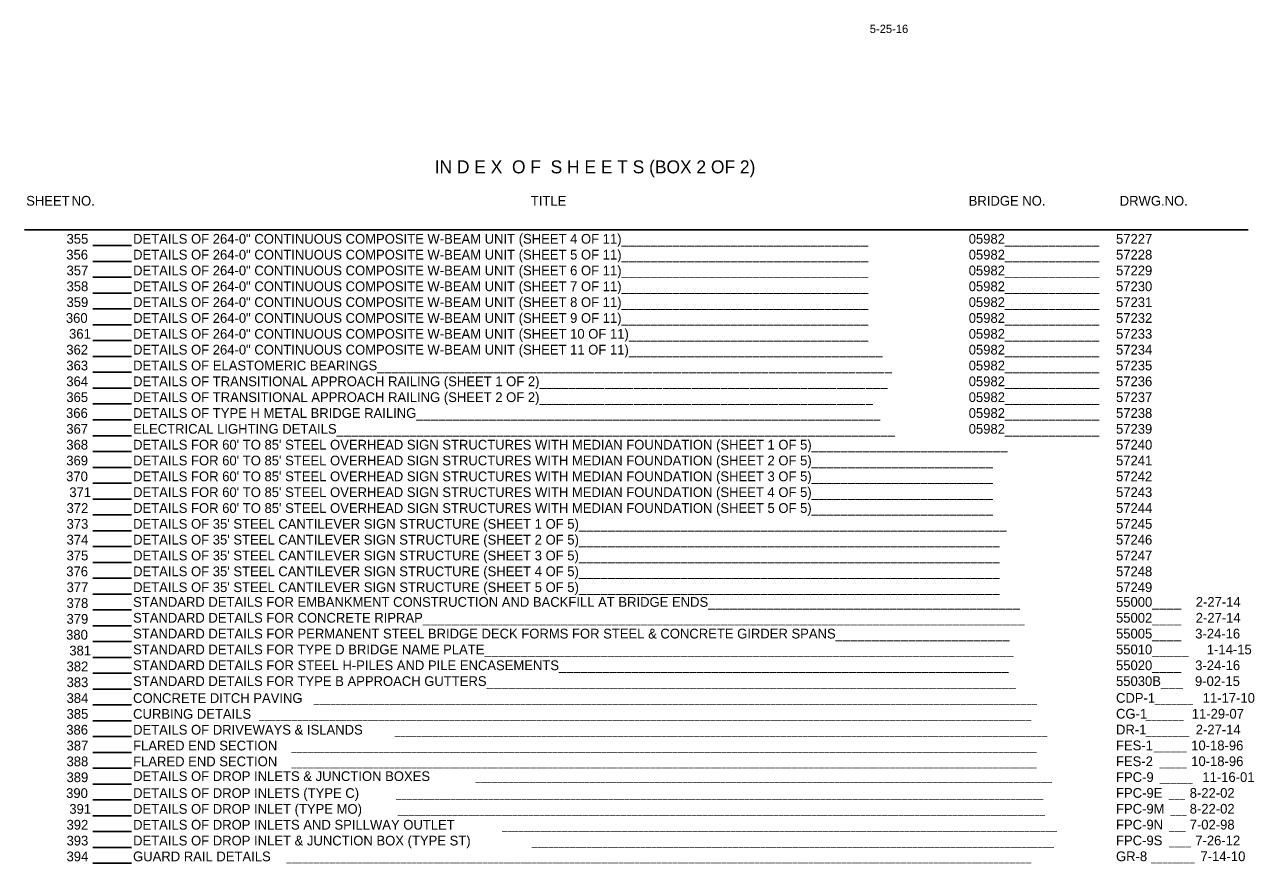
# Model space of a CAD drawing. Extents: x 1224738 to 1230974, y 151304 to 152345.
# Drawn here: x 1227314 to 1227963, y 151881 to 152323 of the extents above; entities that cross this region are included whole.
import ezdxf

# ---------------------------------------------------------------- set-up
doc = ezdxf.new("R2010")
doc.units = 0
for name, color, linetype in [('R_Border', 7, 'Continuous'), ('R_Border Notes', 7, 'Continuous'), ('R_Dimension', 7, 'Continuous')]:
    doc.layers.add(name, color=color, linetype=linetype)

msp = doc.modelspace()

# ---------------------------------------------------------------- linework, layer by layer
at = {"layer": 'R_Border Notes'}
msp.add_line((1227314.16, 152214.98), (1227314.16, 152214.98), dxfattribs=at)
at = {"layer": 'R_Dimension'}
for p, q in [((1227314.16, 152214.98), (1227959.93, 152214.98)), ((1227350.11, 152206.63), (1227370.59, 152206.63)), ((1227350.11, 152198.27), (1227370.59, 152198.27)), ((1227350.11, 152189.91), (1227370.59, 152189.91)), ((1227350.11, 152181.55), (1227370.59, 152181.55)), ((1227350.11, 152173.19), (1227370.59, 152173.19)), ((1227350.11, 152164.83), (1227370.59, 152164.83)), ((1227350.11, 152156.47), (1227370.59, 152156.47)), ((1227350.11, 152148.11), (1227370.59, 152148.11)), ((1227350.11, 152139.75), (1227370.59, 152139.75)), ((1227350.11, 152131.39), (1227370.59, 152131.39)), ((1227350.11, 152123.03), (1227370.59, 152123.03)), ((1227350.11, 152114.67), (1227370.59, 152114.67)), ((1227350.11, 152106.31), (1227370.59, 152106.31)), ((1227350.11, 152097.95), (1227370.59, 152097.95)), ((1227350.11, 152089.59), (1227370.59, 152089.59)), ((1227350.11, 152081.23), (1227370.59, 152081.23)), ((1227350.11, 152072.87), (1227370.59, 152072.87)), ((1227350.11, 152064.52), (1227370.59, 152064.52)), ((1227350.11, 152056.16), (1227370.59, 152056.16)), ((1227350.11, 152047.8), (1227370.59, 152047.8)), ((1227350.11, 152039.44), (1227370.59, 152039.44)), ((1227350.11, 152031.08), (1227370.59, 152031.08)), ((1227350.11, 152022.72), (1227370.59, 152022.72)), ((1227350.11, 152014.36), (1227370.59, 152014.36)), ((1227350.11, 152006), (1227370.59, 152006)), ((1227350.11, 151997.64), (1227370.59, 151997.64)), ((1227350.11, 151989.28), (1227370.59, 151989.28)), ((1227350.11, 151980.92), (1227370.59, 151980.92)), ((1227350.11, 151972.56), (1227370.59, 151972.56)), ((1227350.11, 151964.2), (1227370.59, 151964.2)), ((1227350.11, 151955.84), (1227370.59, 151955.84)), ((1227350.11, 151947.48), (1227370.59, 151947.48)), ((1227350.11, 151939.12), (1227370.59, 151939.12)), ((1227350.11, 151930.76), (1227370.59, 151930.76)), ((1227350.11, 151922.41), (1227370.59, 151922.41)), ((1227350.11, 151914.05), (1227370.59, 151914.05)), ((1227350.11, 151905.69), (1227370.59, 151905.69)), ((1227350.11, 151897.33), (1227370.59, 151897.33)), ((1227350.11, 151888.97), (1227370.59, 151888.97)), ((1227350.11, 151880.61), (1227370.59, 151880.61))]:
    msp.add_line(p, q, dxfattribs=at)

# ---------------------------------------------------------------- texts
at = {"layer": 'R_Border'}
msp.add_text('5-25-16', height=4.396, dxfattribs=at).set_placement((1227760.18, 152318.84))
at = {"layer": 'R_Dimension'}
for s, height, p in [('I', 6.86, (1227530.59, 152244.78)), (' N D E X  O F  S H E E T S (BOX 2 OF 2)', 6.859, (1227530.59, 152244.78)), ('SHEET', 5.144, (1227315, 152227.72)), (' NO.', 5.144, (1227337.07, 152227.72)), ('TITLE', 5.144, (1227581.31, 152227.72)), ('BRIDGE NO.', 5.144, (1227812.38, 152227.72)), ('DRWG.NO.', 5.144, (1227892.08, 152227.72)), ('355', 5.144, (1227336.3, 152207.65)), ('DETAILS OF 264-0" CONTINUOUS COMPOSITE W-BEAM UNIT (SHEET 4 OF 11)__________________________________', 5.1443, (1227371.42, 152207.65)), ('05982_____________', 5.1443, (1227812.38, 152207.65)), ('57227', 5.144, (1227890.12, 152207.65)), ('356', 5.144, (1227336.16, 152199.29)), ('DETAILS OF 264-0" CONTINUOUS COMPOSITE W-BEAM UNIT (SHEET 5 OF 11)__________________________________', 5.1443, (1227371.42, 152199.29)), ('05982_____________', 5.1443, (1227812.38, 152199.29)), ('57228', 5.144, (1227890.12, 152199.29)), ('357', 5.144, (1227336.3, 152190.94)), ('DETAILS OF 264-0" CONTINUOUS COMPOSITE W-BEAM UNIT (SHEET 6 OF 11)__________________________________', 5.1443, (1227371.42, 152190.94)), ('05982_____________', 5.1443, (1227812.38, 152190.94)), ('57229', 5.144, (1227890.12, 152190.94)), ('358', 5.144, (1227336.3, 152182.58)), ('DETAILS OF 264-0" CONTINUOUS COMPOSITE W-BEAM UNIT (SHEET 7 OF 11)__________________________________', 5.1443, (1227371.42, 152182.58)), ('05982_____________', 5.1443, (1227812.38, 152182.58)), ('57230', 5.144, (1227890.12, 152182.58)), ('359', 5.144, (1227336.28, 152174.22)), ('DETAILS OF 264-0" CONTINUOUS COMPOSITE W-BEAM UNIT (SHEET 8 OF 11)__________________________________', 5.1443, (1227371.42, 152174.22)), ('05982_____________', 5.1443, (1227812.38, 152174.22)), ('57231', 5.144, (1227890.12, 152174.22)), ('360', 5.144, (1227335.95, 152165.86)), ('DETAILS OF 264-0" CONTINUOUS COMPOSITE W-BEAM UNIT (SHEET 9 OF 11)__________________________________', 5.1443, (1227371.42, 152165.86)), ('05982_____________', 5.1443, (1227812.38, 152165.86)), ('57232', 5.144, (1227890.12, 152165.86)), ('361', 5.144, (1227337.64, 152157.5)), ('DETAILS OF 264-0" CONTINUOUS COMPOSITE W-BEAM UNIT (SHEET 10 OF 11)_________________________________', 5.1443, (1227371.42, 152157.5)), ('05982_____________', 5.1443, (1227812.38, 152157.5)), ('57233', 5.144, (1227890.12, 152157.5)), ('362', 5.144, (1227336.18, 152149.14)), ('DETAILS OF 264-0" CONTINUOUS COMPOSITE W-BEAM UNIT (SHEET 11 OF 11)___________________________________', 5.14425, (1227371.42, 152149.14)), ('05982_____________', 5.1443, (1227812.38, 152149.14)), ('57234', 5.144, (1227890.12, 152149.14)), ('363', 5.144, (1227336.18, 152140.78)), ('DETAILS OF ELASTOMERIC BEARINGS_______________________________________________________________________', 5.14425, (1227371.42, 152140.78)), ('05982_____________', 5.1443, (1227812.38, 152140.78)), ('57235', 5.144, (1227890.12, 152140.78)), ('364', 5.144, (1227336.18, 152132.42)), ('DETAILS OF TRANSITIONAL APPROACH RAILING (SHEET 1 OF 2)________________________________________________', 5.14425, (1227371.42, 152132.42)), ('05982_____________', 5.1443, (1227812.38, 152132.42)), ('57236', 5.144, (1227890.12, 152132.42)), ('365', 5.144, (1227336.18, 152124.06)), ('DETAILS OF TRANSITIONAL APPROACH RAILING (SHEET 2 OF 2)______________________________________________', 5.14425, (1227371.42, 152124.06)), ('05982_____________', 5.1443, (1227812.38, 152124.06)), ('57237', 5.144, (1227890.12, 152124.06)), ('366', 5.144, (1227336.04, 152115.7)), ('DETAILS OF TYPE H METAL BRIDGE RAILING________________________________________________________________', 5.14425, (1227371.42, 152115.7)), ('05982_____________', 5.1443, (1227812.38, 152115.7)), ('57238', 5.144, (1227890.12, 152115.7)), ('367', 5.144, (1227336.18, 152107.34)), ('ELECTRICAL LIGHTING DETAILS_____________________________________________________________________________', 5.14425, (1227371.42, 152107.34)), ('05982_____________', 5.1443, (1227812.38, 152107.34)), ('57239', 5.144, (1227890.12, 152107.34)), ('368', 5.144, (1227336.18, 152098.98)), ("DETAILS FOR 60' TO 85' STEEL OVERHEAD SIGN STRUCTURES WITH MEDIAN FOUNDATION (SHEET 1 OF 5)___________________________", 5.14425, (1227371.42, 152098.98)), ('57240', 5.144, (1227890.12, 152098.98)), ('369', 5.144, (1227336.16, 152090.62)), ("DETAILS FOR 60' TO 85' STEEL OVERHEAD SIGN STRUCTURES WITH MEDIAN FOUNDATION (SHEET 2 OF 5)_________________________", 5.14425, (1227371.42, 152090.62)), ('57241', 5.144, (1227890.12, 152090.62)), ('370', 5.144, (1227336.08, 152082.26)), ("DETAILS FOR 60' TO 85' STEEL OVERHEAD SIGN STRUCTURES WITH MEDIAN FOUNDATION (SHEET 3 OF 5)_________________________", 5.14425, (1227371.42, 152082.26)), ('57242', 5.144, (1227890.12, 152082.26)), ('371', 5.144, (1227337.76, 152073.9)), ("DETAILS FOR 60' TO 85' STEEL OVERHEAD SIGN STRUCTURES WITH MEDIAN FOUNDATION (SHEET 4 OF 5)_________________________", 5.14425, (1227371.42, 152073.9)), ('57243', 5.144, (1227890.12, 152073.9)), ('372', 5.144, (1227336.3, 152065.54)), ("DETAILS FOR 60' TO 85' STEEL OVERHEAD SIGN STRUCTURES WITH MEDIAN FOUNDATION (SHEET 5 OF 5)_________________________", 5.14425, (1227371.42, 152065.54)), ('57244', 5.144, (1227890.12, 152065.54)), ('373', 5.144, (1227336.3, 152057.18)), ("DETAILS OF 35' STEEL CANTILEVER SIGN STRUCTURE (SHEET 1 OF 5)___________________________________________________________", 5.14425, (1227371.42, 152057.19)), ('57245', 5.144, (1227890.12, 152057.18)), ('374', 5.144, (1227336.3, 152048.83)), ("DETAILS OF 35' STEEL CANTILEVER SIGN STRUCTURE (SHEET 2 OF 5)__________________________________________________________", 5.14425, (1227371.42, 152048.83)), ('57246', 5.144, (1227890.12, 152048.83)), ('375', 5.144, (1227336.3, 152040.47)), ("DETAILS OF 35' STEEL CANTILEVER SIGN STRUCTURE (SHEET 3 OF 5)__________________________________________________________", 5.14425, (1227371.42, 152040.47)), ('57247', 5.144, (1227890.12, 152040.47)), ('376', 5.144, (1227336.16, 152032.11)), ("DETAILS OF 35' STEEL CANTILEVER SIGN STRUCTURE (SHEET 4 OF 5)__________________________________________________________", 5.14425, (1227371.42, 152032.11)), ('57248', 5.144, (1227890.12, 152032.11)), ('377', 5.144, (1227336.3, 152023.75)), ("DETAILS OF 35' STEEL CANTILEVER SIGN STRUCTURE (SHEET 5 OF 5)__________________________________________________________", 5.14425, (1227371.42, 152023.75)), ('57249', 5.144, (1227890.12, 152023.75)), ('378', 5.144, (1227336.3, 152015.39)), ('STANDARD DETAILS FOR EMBANKMENT CONSTRUCTION AND BACKFILL AT BRIDGE ENDS___________________________________________', 5.14425, (1227371.42, 152015.97)), ('55000____', 5.144, (1227890.12, 152015.97)), ('2-27-14', 5.144, (1227932.19, 152015.97)), ('379', 5.144, (1227336.28, 152007.03)), ('STANDARD DETAILS FOR CONCRETE RIPRAP___________________________________________________________________________________', 5.14425, (1227371.42, 152007.61)), ('55002____', 5.144, (1227890.12, 152007.61)), ('2-27-14', 5.144, (1227932.19, 152007.61)), ('380', 5.144, (1227336.08, 151998.67)), ('STANDARD DETAILS FOR PERMANENT STEEL BRIDGE DECK FORMS FOR STEEL & CONCRETE GIRDER SPANS________________________', 5.14425, (1227371.42, 151999.25)), ('55005____', 5.144, (1227890.12, 151999.25)), ('3-24-16', 5.144, (1227931.91, 151999.25)), ('381', 5.144, (1227337.76, 151990.31)), ('STANDARD DETAILS FOR TYPE D BRIDGE NAME PLATE_________________________________________________________________________', 5.14425, (1227371.42, 151990.89)), ('55010_____', 5.144, (1227890.12, 151990.89)), ('1-14-15', 5.144, (1227938.03, 151990.89)), ('382', 5.144, (1227336.3, 151981.95)), ('STANDARD DETAILS FOR STEEL H-PILES AND PILE ENCASEMENTS______________________________________________________________', 5.14425, (1227371.42, 151982.53)), ('55020____', 5.144, (1227890.12, 151982.53)), ('3-24-16', 5.144, (1227931.91, 151982.53)), ('383', 5.144, (1227336.3, 151973.59)), ('STANDARD DETAILS FOR TYPE B APPROACH GUTTERS_________________________________________________________________________ ', 5.14425, (1227371.42, 151974.17)), ('55030B___', 5.144, (1227890.12, 151974.17)), ('9-02-15', 5.144, (1227931.79, 151974.17)), ('384', 5.144, (1227336.3, 151965.23)), ('CONCRETE DITCH PAVING', 5.1443, (1227371.42, 151965.23)), ('CDP-1', 5.144, (1227890.12, 151965.31)), ('11-17-10', 5.144, (1227935.88, 151965.31)), ('385', 5.144, (1227336.3, 151956.87)), ('CURBING DETAILS', 5.1443, (1227371.42, 151956.87)), ('_____________________________________________________________________________________________________________________________________', 3.85819, (1227466.77, 151965.23)), ('CG-1', 5.144, (1227890.12, 151956.95)), ('_______', 3.858, (1227910.62, 151965.31)), ('11-29-07', 5.144, (1227930.09, 151956.95)), ('386', 5.144, (1227336.16, 151948.51)), ('DETAILS OF DRIVEWAYS & ISLANDS', 5.1443, (1227371.42, 151948.51)), ('______________________________________________________________________________________________________________________________________________', 3.85819, (1227437.93, 151956.87)), ('DR-1', 5.144, (1227890.12, 151948.59)), ('_______', 3.858, (1227905.76, 151956.95)), ('2-27-14', 5.144, (1227932.19, 151948.59)), ('________________________________________________________________________________________________________________________', 3.85819, (1227509.47, 151948.51)), ('________', 3.858, (1227905.76, 151948.59)), ('387', 5.144, (1227336.3, 151940.15)), ('FLARED END SECTION', 5.1443, (1227371.42, 151940.15)), ('FES-1', 5.144, (1227890.12, 151940.23)), ('10-18-96', 5.144, (1227929.8, 151940.23)), ('388', 5.144, (1227336.3, 151931.79)), ('FLARED END SECTION', 5.1443, (1227371.42, 151931.79)), ('_________________________________________________________________________________________________________________________________________', 3.85819, (1227455.03, 151940.15)), ('FES-2', 5.144, (1227890.12, 151931.87)), ('______', 3.858, (1227910.13, 151940.23)), ('10-18-96', 5.144, (1227929.8, 151931.87)), ('389', 5.144, (1227336.28, 151923.43)), ('DETAILS OF DROP INLETS & JUNCTION BOXES', 5.1443, (1227371.42, 151924.01)), ('_________________________________________________________________________________________________________________________________________', 3.85819, (1227455.03, 151931.79)), ('FPC-9', 5.144, (1227890.12, 151923.51)), ('_____', 3.858, (1227913.05, 151931.87)), ('11-16-01', 5.144, (1227935.68, 151923.51)), ('__________________________________________________________________________________________________________', 3.85819, (1227552.08, 151924.01)), ('______', 3.858, (1227913.29, 151923.51)), ('390', 5.144, (1227336.08, 151915.07)), ('DETAILS OF DROP INLETS (TYPE C)', 5.1443, (1227371.42, 151915.08)), ('FPC-9E', 5.144, (1227890.12, 151915.15)), ('8-22-02', 5.144, (1227929, 151915.15)), ('391', 5.144, (1227337.76, 151906.72)), ('DETAILS OF DROP INLET (TYPE MO)', 5.1443, (1227371.42, 151906.72)), ('_______________________________________________________________________________________________________________________', 3.85819, (1227510.2, 151915.08)), ('FPC-9M', 5.144, (1227890.12, 151906.79)), ('___', 3.858, (1227917.91, 151915.15)), ('8-22-02', 5.144, (1227929, 151906.79)), ('392', 5.144, (1227336.3, 151898.36)), ('DETAILS OF DROP INLETS AND SPILLWAY OUTLET', 5.1443, (1227371.42, 151898.36)), ('_______________________________________________________________________________________________________________________', 3.85819, (1227511.17, 151906.72)), ('FPC-9N', 5.144, (1227890.12, 151898.43)), ('___', 3.858, (1227918.8, 151906.79)), ('7-02-98', 5.144, (1227929, 151898.43)), ('393', 5.144, (1227336.3, 151890)), ('DETAILS OF DROP INLET & JUNCTION BOX (TYPE ST)', 5.1443, (1227371.42, 151890)), ('______________________________________________________________________________________________________', 3.85819, (1227566.18, 151898.36)), ('FPC-9S', 5.144, (1227890.12, 151890.07)), ('___', 3.858, (1227918.15, 151898.43)), ('7-26-12', 5.144, (1227931.95, 151890.07)), ('________________________________________________________________________________________________', 3.8582, (1227581.81, 151890)), ('____', 3.858, (1227918.15, 151890.07)), ('394', 5.144, (1227336.3, 151881.64)), ('GUARD RAIL DETAILS', 5.1443, (1227371.42, 151881.64)), ('GR-8', 5.144, (1227890.12, 151881.71)), ('7-14-10', 5.144, (1227934.67, 151881.71)), ('_________________________________________________________________________________________________________________________________________', 3.85819, (1227452.35, 151881.64)), ('________', 3.858, (1227908.68, 151881.71))]:
    msp.add_text(s, height=height, dxfattribs=at).set_placement(p)

doc.saveas('drawing.dxf')
